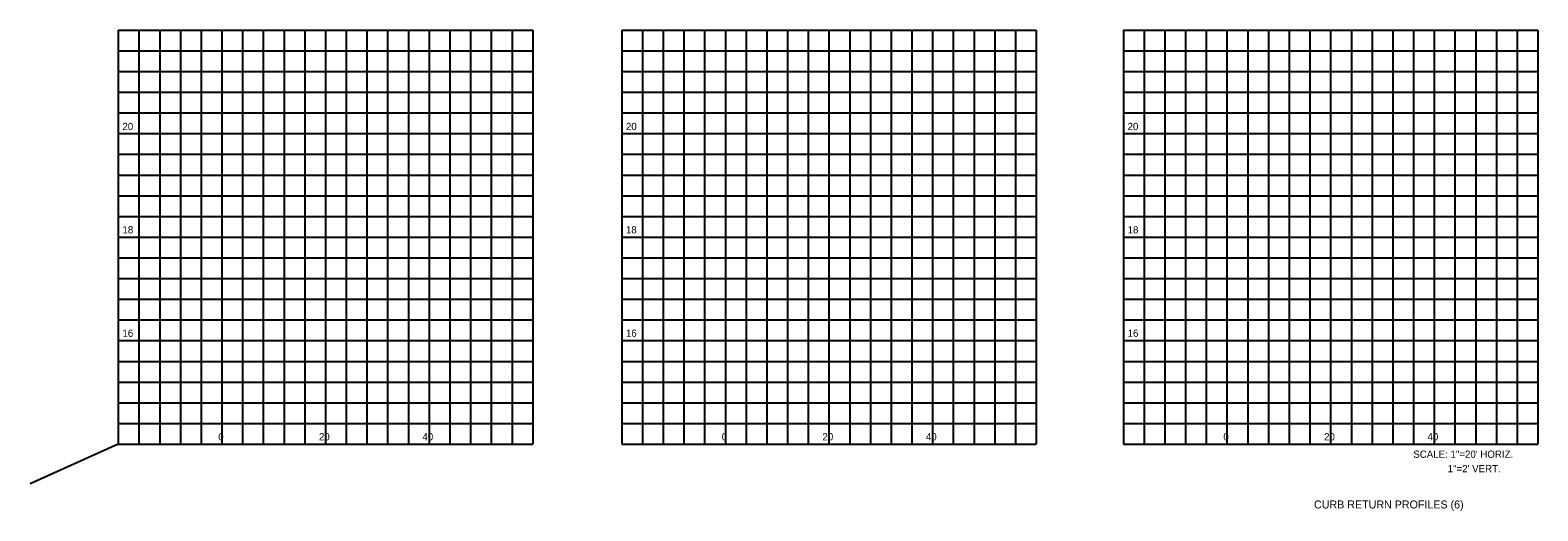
# Model space of a CAD drawing. Extents: x 127723 to 128378, y 21426 to 23736.
# Drawn here: x 127722.5 to 128013.5, y 21806.5 to 21899.4 of the extents above; entities that cross this region are included whole.
import ezdxf

# ---------------------------------------------------------------- set-up
doc = ezdxf.new("R2010")
doc.units = 0
for name, color, linetype in [('Default', 7, 'Continuous'), ('GroundCover', 7, 'Continuous'), ('Miscellaneous0', 7, 'Continuous'), ('SheetBorder_dp', 7, 'Continuous'), ('TextNotes', 7, 'Continuous')]:
    doc.layers.add(name, color=color, linetype=linetype)

msp = doc.modelspace()

# ---------------------------------------------------------------- linework, layer by layer
at = {"layer": 'Miscellaneous0'}
for p, q in [((127743.54, 21899.36), (127743.54, 21819.36)), ((127747.54, 21899.36), (127747.54, 21819.36)), ((127751.54, 21899.36), (127751.54, 21819.36)), ((127755.54, 21899.36), (127755.54, 21819.36)), ((127763.54, 21899.36), (127763.54, 21819.36)), ((127767.54, 21899.36), (127767.54, 21819.36)), ((127771.54, 21899.36), (127771.54, 21819.36)), ((127775.54, 21899.36), (127775.54, 21819.36)), ((127783.54, 21899.36), (127783.54, 21819.36)), ((127787.54, 21899.36), (127787.54, 21819.36)), ((127791.54, 21899.36), (127791.54, 21819.36)), ((127795.54, 21899.36), (127795.54, 21819.36)), ((127803.54, 21899.36), (127803.54, 21819.36)), ((127807.54, 21899.36), (127807.54, 21819.36)), ((127811.54, 21899.36), (127811.54, 21819.36)), ((127815.54, 21899.36), (127815.54, 21819.36)), ((127840.72, 21899.36), (127840.72, 21819.36)), ((127844.72, 21899.36), (127844.72, 21819.36)), ((127848.72, 21899.36), (127848.72, 21819.36)), ((127852.72, 21899.36), (127852.72, 21819.36)), ((127860.72, 21899.36), (127860.72, 21819.36)), ((127864.72, 21899.36), (127864.72, 21819.36)), ((127868.72, 21899.36), (127868.72, 21819.36)), ((127872.72, 21899.36), (127872.72, 21819.36)), ((127880.72, 21899.36), (127880.72, 21819.36)), ((127884.72, 21899.36), (127884.72, 21819.36)), ((127888.72, 21899.36), (127888.72, 21819.36)), ((127892.72, 21899.36), (127892.72, 21819.36)), ((127900.72, 21899.36), (127900.72, 21819.36)), ((127904.72, 21899.36), (127904.72, 21819.36)), ((127908.72, 21899.36), (127908.72, 21819.36)), ((127912.72, 21899.36), (127912.72, 21819.36)), ((127937.54, 21899.36), (127937.54, 21819.36)), ((127941.54, 21899.36), (127941.54, 21819.36)), ((127945.54, 21899.36), (127945.54, 21819.36)), ((127949.54, 21899.36), (127949.54, 21819.36)), ((127957.54, 21899.36), (127957.54, 21819.36)), ((127961.54, 21899.36), (127961.54, 21819.36)), ((127965.54, 21899.36), (127965.54, 21819.36)), ((127969.54, 21899.36), (127969.54, 21819.36)), ((127977.54, 21899.36), (127977.54, 21819.36)), ((127981.54, 21899.36), (127981.54, 21819.36)), ((127985.54, 21899.36), (127985.54, 21819.36)), ((127989.54, 21899.36), (127989.54, 21819.36)), ((127997.54, 21899.36), (127997.54, 21819.36)), ((128001.54, 21899.36), (128001.54, 21819.36)), ((128005.54, 21899.36), (128005.54, 21819.36)), ((128009.54, 21899.36), (128009.54, 21819.36)), ((127739.54, 21895.36), (127819.54, 21895.36)), ((127836.72, 21895.36), (127916.72, 21895.36)), ((127933.54, 21895.36), (128013.54, 21895.36)), ((127739.54, 21891.36), (127819.54, 21891.36)), ((127836.72, 21891.36), (127916.72, 21891.36)), ((127933.54, 21891.36), (128013.54, 21891.36)), ((127739.54, 21887.36), (127819.54, 21887.36)), ((127836.72, 21887.36), (127916.72, 21887.36)), ((127933.54, 21887.36), (128013.54, 21887.36)), ((127739.54, 21883.36), (127819.54, 21883.36)), ((127836.72, 21883.36), (127916.72, 21883.36)), ((127933.54, 21883.36), (128013.54, 21883.36)), ((127739.54, 21875.36), (127819.54, 21875.36)), ((127836.72, 21875.36), (127916.72, 21875.36)), ((127933.54, 21875.36), (128013.54, 21875.36)), ((127739.54, 21871.36), (127819.54, 21871.36)), ((127836.72, 21871.36), (127916.72, 21871.36)), ((127933.54, 21871.36), (128013.54, 21871.36)), ((127739.54, 21867.36), (127819.54, 21867.36)), ((127836.72, 21867.36), (127916.72, 21867.36)), ((127933.54, 21867.36), (128013.54, 21867.36)), ((127739.54, 21863.36), (127819.54, 21863.36)), ((127836.72, 21863.36), (127916.72, 21863.36)), ((127933.54, 21863.36), (128013.54, 21863.36)), ((127739.54, 21855.36), (127819.54, 21855.36)), ((127836.72, 21855.36), (127916.72, 21855.36)), ((127933.54, 21855.36), (128013.54, 21855.36)), ((127739.54, 21851.36), (127819.54, 21851.36)), ((127836.72, 21851.36), (127916.72, 21851.36)), ((127933.54, 21851.36), (128013.54, 21851.36)), ((127739.54, 21847.36), (127819.54, 21847.36)), ((127836.72, 21847.36), (127916.72, 21847.36)), ((127933.54, 21847.36), (128013.54, 21847.36)), ((127739.54, 21843.36), (127819.54, 21843.36)), ((127836.72, 21843.36), (127916.72, 21843.36)), ((127933.54, 21843.36), (128013.54, 21843.36)), ((127739.54, 21835.36), (127819.54, 21835.36)), ((127836.72, 21835.36), (127916.72, 21835.36)), ((127933.54, 21835.36), (128013.54, 21835.36)), ((127739.54, 21831.36), (127819.54, 21831.36)), ((127836.72, 21831.36), (127916.72, 21831.36)), ((127933.54, 21831.36), (128013.54, 21831.36)), ((127739.54, 21827.36), (127819.54, 21827.36)), ((127836.72, 21827.36), (127916.72, 21827.36)), ((127933.54, 21827.36), (128013.54, 21827.36)), ((127739.54, 21823.36), (127819.54, 21823.36)), ((127836.72, 21823.36), (127916.72, 21823.36)), ((127933.54, 21823.36), (128013.54, 21823.36))]:
    msp.add_line(p, q, dxfattribs=at)
at = {"layer": 'SheetBorder_dp'}
for p, q in [((127739.54, 21899.36), (127819.54, 21899.36)), ((127739.54, 21899.36), (127739.54, 21819.36)), ((127759.54, 21899.36), (127759.54, 21839.36)), ((127759.54, 21899.36), (127759.54, 21819.36)), ((127779.54, 21899.36), (127779.54, 21819.36)), ((127799.54, 21899.36), (127799.54, 21819.36)), ((127819.54, 21899.36), (127819.54, 21819.36)), ((127836.72, 21899.36), (127916.72, 21899.36)), ((127836.72, 21899.36), (127836.72, 21819.36)), ((127856.72, 21899.36), (127856.72, 21839.36)), ((127856.72, 21899.36), (127856.72, 21819.36)), ((127876.72, 21899.36), (127876.72, 21819.36)), ((127896.72, 21899.36), (127896.72, 21819.36)), ((127916.72, 21899.36), (127916.72, 21819.36)), ((127933.54, 21899.36), (128013.54, 21899.36)), ((127933.54, 21899.36), (127933.54, 21819.36)), ((127953.54, 21899.36), (127953.54, 21839.36)), ((127953.54, 21899.36), (127953.54, 21819.36)), ((127973.54, 21899.36), (127973.54, 21819.36)), ((127993.54, 21899.36), (127993.54, 21819.36)), ((128013.54, 21899.36), (128013.54, 21819.36)), ((127739.54, 21879.36), (127819.54, 21879.36)), ((127836.72, 21879.36), (127916.72, 21879.36)), ((127933.54, 21879.36), (128013.54, 21879.36)), ((127739.54, 21859.36), (127819.54, 21859.36)), ((127836.72, 21859.36), (127916.72, 21859.36)), ((127933.54, 21859.36), (128013.54, 21859.36)), ((127739.54, 21839.36), (127819.54, 21839.36)), ((127739.54, 21839.36), (127819.54, 21839.36)), ((127836.72, 21839.36), (127916.72, 21839.36)), ((127836.72, 21839.36), (127916.72, 21839.36)), ((127933.54, 21839.36), (128013.54, 21839.36)), ((127933.54, 21839.36), (128013.54, 21839.36)), ((127739.54, 21819.36), (127819.54, 21819.36)), ((127836.72, 21819.36), (127916.72, 21819.36)), ((127933.54, 21819.36), (128013.54, 21819.36))]:
    msp.add_line(p, q, dxfattribs=at)
at = {"layer": 'TextNotes'}
msp.add_line((127739.54, 21819.38), (127722.54, 21811.72), dxfattribs=at)

# ---------------------------------------------------------------- texts
at = {"layer": 'Default'}
msp.add_text('CURB RETURN PROFILES (6)', height=1.5418, dxfattribs=at).set_placement((127970.34, 21806.94))
at = {"layer": 'GroundCover'}
for s, p in [('20', (127740.35, 21880.04)), ('20', (127837.53, 21880.04)), ('20', (127934.35, 21880.04)), ('18', (127740.35, 21860.08)), ('18', (127837.53, 21860.08)), ('18', (127934.35, 21860.08)), ('16', (127740.35, 21840.1)), ('16', (127837.53, 21840.1)), ('16', (127934.35, 21840.1)), ('0', (127758.84, 21820.1)), ('20', (127778.28, 21820.1)), ('40', (127798.24, 21820.1)), ('0', (127856.02, 21820.1)), ('20', (127875.46, 21820.1)), ('40', (127895.42, 21820.1)), ('0', (127952.84, 21820.1)), ('20', (127972.28, 21820.1)), ('40', (127992.24, 21820.1)), ('SCALE: 1"=20\' HORIZ.', (127989.5, 21816.73)), ('  1"=2\' VERT.', (127995.1, 21813.93))]:
    msp.add_text(s, height=1.4, dxfattribs=at).set_placement(p)

doc.saveas('drawing.dxf')
